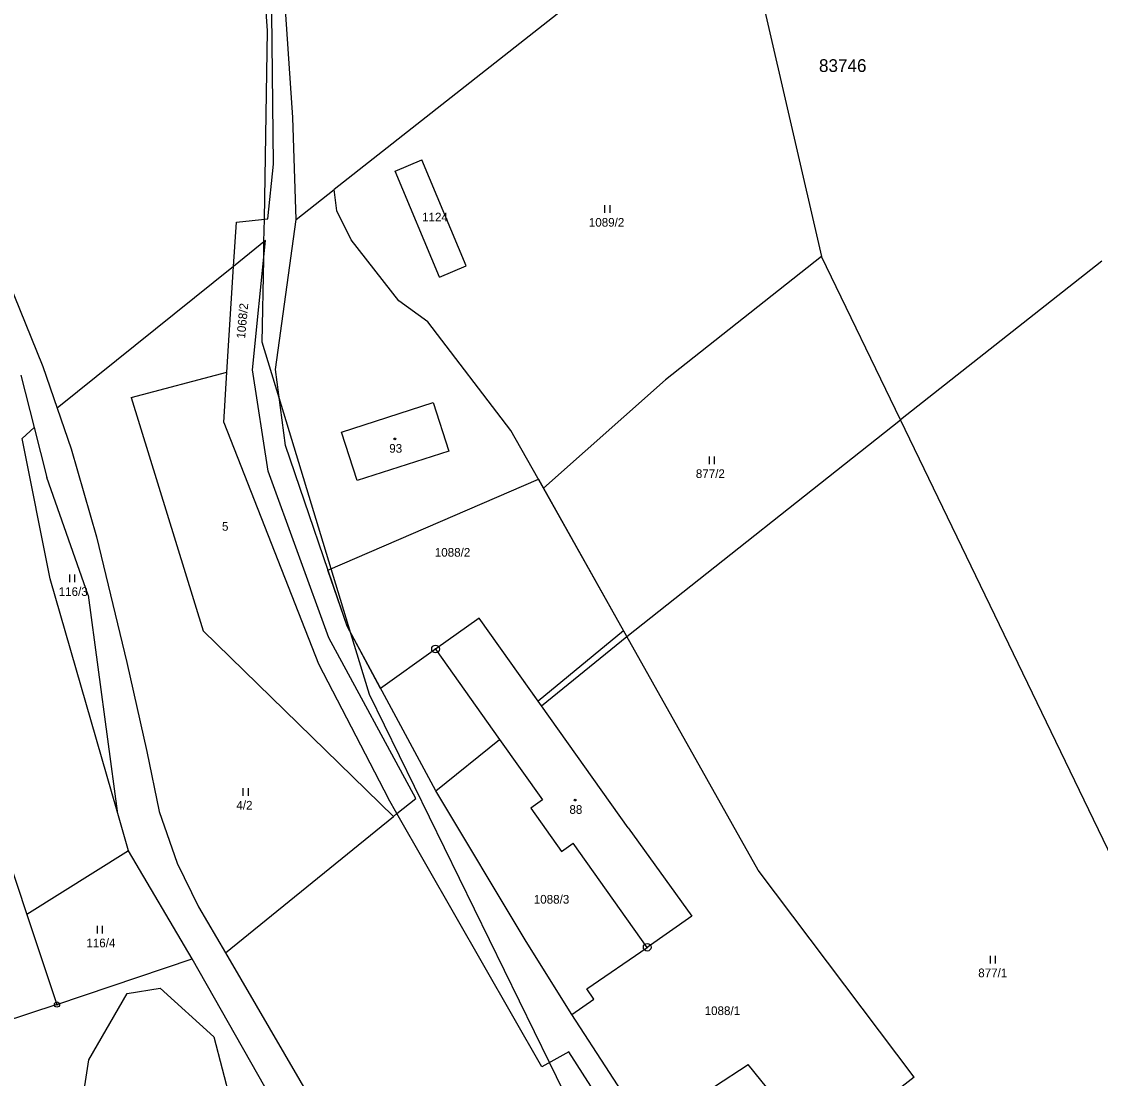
# Model space of a CAD drawing. Extents: x -547623 to -538651, y -1096714 to -1086522.
# Drawn here: x -539955.7 to -539744.3, y -1092227.2 to -1092020.2 of the extents above; entities that cross this region are included whole.
import ezdxf

# ---------------------------------------------------------------- set-up
doc = ezdxf.new("R2010")
doc.units = 0
for name, color, linetype in [('Vrstva 1', 7, 'Continuous'), ('Vrstva 25', 7, 'Continuous'), ('Vrstva 30', 7, 'Continuous'), ('Vrstva 52', 7, 'Continuous'), ('Vrstva 53', 7, 'Continuous'), ('Vrstva 83', 7, 'Continuous'), ('Vrstva 86', 7, 'Continuous'), ('Vrstva 90', 7, 'Continuous'), ('Vrstva 92', 7, 'Continuous')]:
    doc.layers.add(name, color=color, linetype=linetype)

msp = doc.modelspace()

# ---------------------------------------------------------------- linework, layer by layer
at = {"layer": 'Vrstva 1'}
for points in [[(-539816.21, -1091991.51), (-539894.46, -1092053.09)], [(-539816.21, -1091991.51), (-539798.97, -1092066.21)], [(-539902.5, -1092038.96), (-539904.83, -1092005.32)], [(-539906.34, -1092048.11), (-539906.65, -1092018.56)], [(-539901.89, -1092058.93), (-539902.5, -1092038.96)], [(-539882.49, -1092049.49), (-539877.28, -1092047.3)], [(-539868.58, -1092068.05), (-539877.28, -1092047.3)], [(-539907.43, -1092058.83), (-539906.34, -1092048.11)], [(-539873.79, -1092070.24), (-539882.49, -1092049.49)], [(-539901.89, -1092058.93), (-539894.46, -1092053.09)], [(-539893.93, -1092057.24), (-539894.46, -1092053.09)], [(-539891.07, -1092062.97), (-539893.93, -1092057.24)], [(-539962.89, -1092059.71), (-539951.46, -1092087.77)], [(-539914.12, -1092068.14), (-539913.58, -1092059.46)], [(-539913.58, -1092059.46), (-539907.43, -1092058.83)], [(-539905.9, -1092088.34), (-539901.89, -1092058.93)], [(-539907.86, -1092063.1), (-539914.12, -1092068.14)], [(-539910.42, -1092088.38), (-539907.86, -1092063.1)], [(-539881.77, -1092074.9), (-539891.07, -1092062.97)], [(-539798.97, -1092066.21), (-539829.53, -1092090.38)], [(-539783.53, -1092098.17), (-539798.97, -1092066.21)], [(-539914.12, -1092068.14), (-539948.66, -1092095.91)], [(-539915.42, -1092088.83), (-539914.12, -1092068.14)], [(-539873.79, -1092070.24), (-539868.58, -1092068.05)], [(-539744.04, -1092067.15), (-539783.53, -1092098.17)], [(-539876.09, -1092079.01), (-539881.77, -1092074.9)], [(-539859.83, -1092100.25), (-539876.09, -1092079.01)], [(-539951.46, -1092087.77), (-539948.66, -1092095.91)], [(-539955.79, -1092089.46), (-539953.19, -1092099.7)], [(-539934.18, -1092093.8), (-539915.42, -1092088.83)], [(-539916.04, -1092098.69), (-539915.42, -1092088.83)], [(-539907.38, -1092108.27), (-539910.42, -1092088.38)], [(-539903.99, -1092103.23), (-539905.9, -1092088.34)], [(-539829.53, -1092090.38), (-539853.45, -1092111.58)], [(-539934.18, -1092093.8), (-539920.06, -1092139.52)], [(-539948.66, -1092095.91), (-539945.93, -1092103.86)], [(-539893, -1092100.58), (-539875.06, -1092094.8)], [(-539875.06, -1092094.8), (-539871.99, -1092104.32)], [(-539837.1, -1092140.63), (-539783.53, -1092098.17)], [(-539700.47, -1092270.14), (-539783.53, -1092098.17)], [(-539955.52, -1092101.83), (-539953.19, -1092099.7)], [(-539953.19, -1092099.7), (-539950.7, -1092109.48)], [(-539916.04, -1092098.69), (-539897.51, -1092145.99)], [(-539889.93, -1092110.1), (-539893, -1092100.58)], [(-539853.45, -1092111.58), (-539859.83, -1092100.25)], [(-539950.06, -1092129.33), (-539955.52, -1092101.83)], [(-539945.93, -1092103.86), (-539940.98, -1092121.12)], [(-539891.91, -1092138.61), (-539903.99, -1092103.23)], [(-539871.99, -1092104.32), (-539889.93, -1092110.1)], [(-539895.5, -1092140.88), (-539907.38, -1092108.27)], [(-539942.59, -1092132.54), (-539950.7, -1092109.48)], [(-539837.1, -1092140.63), (-539853.45, -1092111.58)], [(-539940.98, -1092121.12), (-539935.02, -1092145.71)], [(-539936.95, -1092174.81), (-539950.06, -1092129.33)], [(-539942.59, -1092132.54), (-539936.95, -1092174.81)], [(-539874.52, -1092170.87), (-539891.91, -1092138.61)], [(-539866.04, -1092137.02), (-539874.6, -1092143.1)], [(-539853.85, -1092154.17), (-539866.04, -1092137.02)], [(-539920.06, -1092139.52), (-539882.8, -1092175.84)], [(-539878.46, -1092172.35), (-539895.5, -1092140.88)], [(-539853.85, -1092154.17), (-539837.1, -1092140.63)], [(-539811.35, -1092186.35), (-539837.1, -1092140.63)], [(-539874.6, -1092143.1), (-539862.04, -1092160.78)], [(-539935.02, -1092145.71), (-539931.12, -1092163.12)], [(-539897.51, -1092145.99), (-539883.81, -1092172.41)], [(-539836.84, -1092178.1), (-539853.85, -1092154.17)], [(-539874.52, -1092170.87), (-539862.04, -1092160.78)], [(-539862.04, -1092160.78), (-539853.63, -1092172.61)], [(-539931.12, -1092163.12), (-539928.71, -1092174.89)], [(-539962.42, -1092171.72), (-539954.61, -1092195.07)], [(-539882.14, -1092175.31), (-539883.81, -1092172.41)], [(-539882.14, -1092175.31), (-539878.46, -1092172.35)], [(-539856.84, -1092200.36), (-539874.52, -1092170.87)], [(-539853.63, -1092172.61), (-539855.91, -1092174.23)], [(-539855.91, -1092174.23), (-539849.89, -1092182.71)], [(-539934.71, -1092182.57), (-539936.95, -1092174.81)], [(-539928.71, -1092174.89), (-539925.21, -1092185)], [(-539915.71, -1092202.56), (-539882.8, -1092175.84)], [(-539882.8, -1092175.84), (-539882.14, -1092175.31)], [(-539853.75, -1092224.87), (-539882.14, -1092175.31)], [(-539836.84, -1092178.1), (-539824.37, -1092195.39)], [(-539849.89, -1092182.71), (-539847.6, -1092181.08)], [(-539833.15, -1092201.49), (-539847.6, -1092181.08)], [(-539934.71, -1092182.57), (-539954.61, -1092195.07)], [(-539922.21, -1092203.72), (-539934.71, -1092182.57)], [(-539925.21, -1092185), (-539920.97, -1092193.54)], [(-539780.81, -1092226.91), (-539811.35, -1092186.35)], [(-539920.97, -1092193.54), (-539915.71, -1092202.56)], [(-539954.61, -1092195.07), (-539948.72, -1092212.69)], [(-539824.37, -1092195.39), (-539833.15, -1092201.49)], [(-539847.87, -1092214.65), (-539856.84, -1092200.36)], [(-539844.96, -1092209.64), (-539833.15, -1092201.49)], [(-539948.72, -1092212.69), (-539922.21, -1092203.72)], [(-539880.92, -1092276.53), (-539922.21, -1092203.72)], [(-539915.71, -1092202.56), (-539889.59, -1092247.38)], [(-539843.56, -1092211.63), (-539844.96, -1092209.64)], [(-539948.72, -1092212.69), (-539965.3, -1092218.08)], [(-539847.87, -1092214.65), (-539843.56, -1092211.63)], [(-539833.12, -1092237.38), (-539847.87, -1092214.65)], [(-539848.45, -1092221.97), (-539853.75, -1092224.87)], [(-539841.45, -1092232.84), (-539848.45, -1092221.97)], [(-539833.12, -1092237.38), (-539813.33, -1092224.44)], [(-539799.56, -1092241.44), (-539813.33, -1092224.44)], [(-539780.81, -1092226.91), (-539788.2, -1092232.64)]]:
    msp.add_lwpolyline(points, dxfattribs=at)
at = {"layer": 'Vrstva 25'}
for p, q in [((-539841.4, -1092057.67), (-539841.4, -1092056.17)), ((-539840.4, -1092057.67), (-539840.4, -1092056.17)), ((-539820.91, -1092106.88), (-539820.91, -1092105.38)), ((-539819.91, -1092106.88), (-539819.91, -1092105.38)), ((-539946.21, -1092129.98), (-539946.21, -1092128.48)), ((-539945.21, -1092129.98), (-539945.21, -1092128.48)), ((-539912.24, -1092171.81), (-539912.24, -1092170.31)), ((-539911.24, -1092171.81), (-539911.24, -1092170.31)), ((-539940.79, -1092198.78), (-539940.79, -1092197.28)), ((-539939.79, -1092198.78), (-539939.79, -1092197.28)), ((-539765.87, -1092204.64), (-539765.87, -1092203.14)), ((-539764.87, -1092204.64), (-539764.87, -1092203.14))]:
    msp.add_line(p, q, dxfattribs=at)
for centre in [(-539882.54, -1092101.93), (-539847.25, -1092172.65)]:
    msp.add_circle(centre, 0.175, dxfattribs=at)
at = {"layer": 'Vrstva 30'}
for points in [[(-539895.65, -1092127.64), (-539854.43, -1092109.84)], [(-539854.43, -1092109.84), (-539853.45, -1092111.58)], [(-539853.45, -1092111.58), (-539837.74, -1092139.49)], [(-539891.91, -1092138.61), (-539895.65, -1092127.64)], [(-539885.34, -1092150.8), (-539891.91, -1092138.61)], [(-539866.04, -1092137.02), (-539874.6, -1092143.1)], [(-539854.5, -1092153.26), (-539866.04, -1092137.02)], [(-539837.74, -1092139.49), (-539854.5, -1092153.26)], [(-539874.6, -1092143.1), (-539885.34, -1092150.8)]]:
    msp.add_lwpolyline(points, dxfattribs=at)
at = {"layer": 'Vrstva 52'}
for points in [[(-539831.5, -1092266.5), (-539852.26, -1092224.05), (-539887.5, -1092152), (-539891.14, -1092140.04), (-539905.19, -1092093.88), (-539908.5, -1092083), (-539908.23, -1092066.8), (-539908.18, -1092063.36), (-539908.1, -1092058.9), (-539907.5, -1092022), (-539909, -1092000.5), (-539909.18, -1092000), (-539912.03, -1091991.9), (-539916.13, -1091980.3), (-539918, -1091975), (-539918, -1091939), (-539927, -1091817.5), (-539926, -1091750), (-539925.89, -1091749.42), (-539921.8, -1091726.73), (-539914.38, -1091685.65), (-539913, -1091678), (-539910.5, -1091683)], [(-539928.63, -1092276.59), (-539933.88, -1092262.01), (-539943.63, -1092242.29), (-539944.5, -1092241.32), (-539945, -1092240), (-539942.5, -1092223.5), (-539935, -1092210.5), (-539928.5, -1092209.5), (-539918, -1092219), (-539914.75, -1092231.55), (-539907.5, -1092259.5), (-539909.06, -1092267.94), (-539910, -1092273), (-539914, -1092278.5)]]:
    msp.add_lwpolyline(points, dxfattribs=at)
at = {"layer": 'Vrstva 83'}
for centre, radius in [((-539874.58, -1092143.07), 0.75), ((-539874.58, -1092143.07), 0.1), ((-539833.12, -1092201.47), 0.75), ((-539833.12, -1092201.47), 0.1), ((-539948.72, -1092212.69), 0.5), ((-539948.72, -1092212.69), 0.1)]:
    msp.add_circle(centre, radius, dxfattribs=at)
at = {"layer": 'Vrstva 90'}
for points in [[(-539893, -1092100.58), (-539875.06, -1092094.8)], [(-539875.06, -1092094.8), (-539871.99, -1092104.32)], [(-539889.93, -1092110.1), (-539893, -1092100.58)], [(-539871.99, -1092104.32), (-539889.93, -1092110.1)], [(-539866.04, -1092137.02), (-539874.6, -1092143.1)], [(-539853.85, -1092154.17), (-539866.04, -1092137.02)], [(-539874.6, -1092143.1), (-539862.04, -1092160.78)], [(-539836.84, -1092178.1), (-539853.85, -1092154.17)], [(-539862.04, -1092160.78), (-539853.63, -1092172.61)], [(-539853.63, -1092172.61), (-539855.91, -1092174.23)], [(-539855.91, -1092174.23), (-539849.89, -1092182.71)], [(-539836.84, -1092178.1), (-539824.37, -1092195.39)], [(-539849.89, -1092182.71), (-539847.6, -1092181.08)], [(-539833.15, -1092201.49), (-539847.6, -1092181.08)], [(-539824.37, -1092195.39), (-539833.15, -1092201.49)]]:
    msp.add_lwpolyline(points, dxfattribs=at)

# ---------------------------------------------------------------- texts
at = {"layer": 'Vrstva 53'}
msp.add_text('83746', height=2.5, dxfattribs=at).set_placement((-539799.47, -1092030.07))
at = {"layer": 'Vrstva 86'}
for s, p in [('1124', (-539877.21, -1092059.33)), ('1089/2', (-539844.55, -1092060.37)), ('877/2', (-539823.59, -1092109.58)), ('5', (-539916.4, -1092119.91)), ('1088/2', (-539874.72, -1092124.99)), ('116/3', (-539948.39, -1092132.68)), ('4/2', (-539913.58, -1092174.51)), ('1088/3', (-539855.33, -1092192.93)), ('116/4', (-539942.97, -1092201.48)), ('877/1', (-539768.28, -1092207.34)), ('1088/1', (-539821.87, -1092214.75))]:
    msp.add_text(s, height=1.7, dxfattribs=at).set_placement(p)
msp.add_text('1068/2', height=1.7, rotation=84.7057, dxfattribs=at).set_placement((-539911.89, -1092082.35))
at = {"layer": 'Vrstva 92'}
for s, p in [('93', (-539883.64, -1092104.63)), ('88', (-539848.35, -1092175.35))]:
    msp.add_text(s, height=1.7, dxfattribs=at).set_placement(p)

doc.saveas('drawing.dxf')
